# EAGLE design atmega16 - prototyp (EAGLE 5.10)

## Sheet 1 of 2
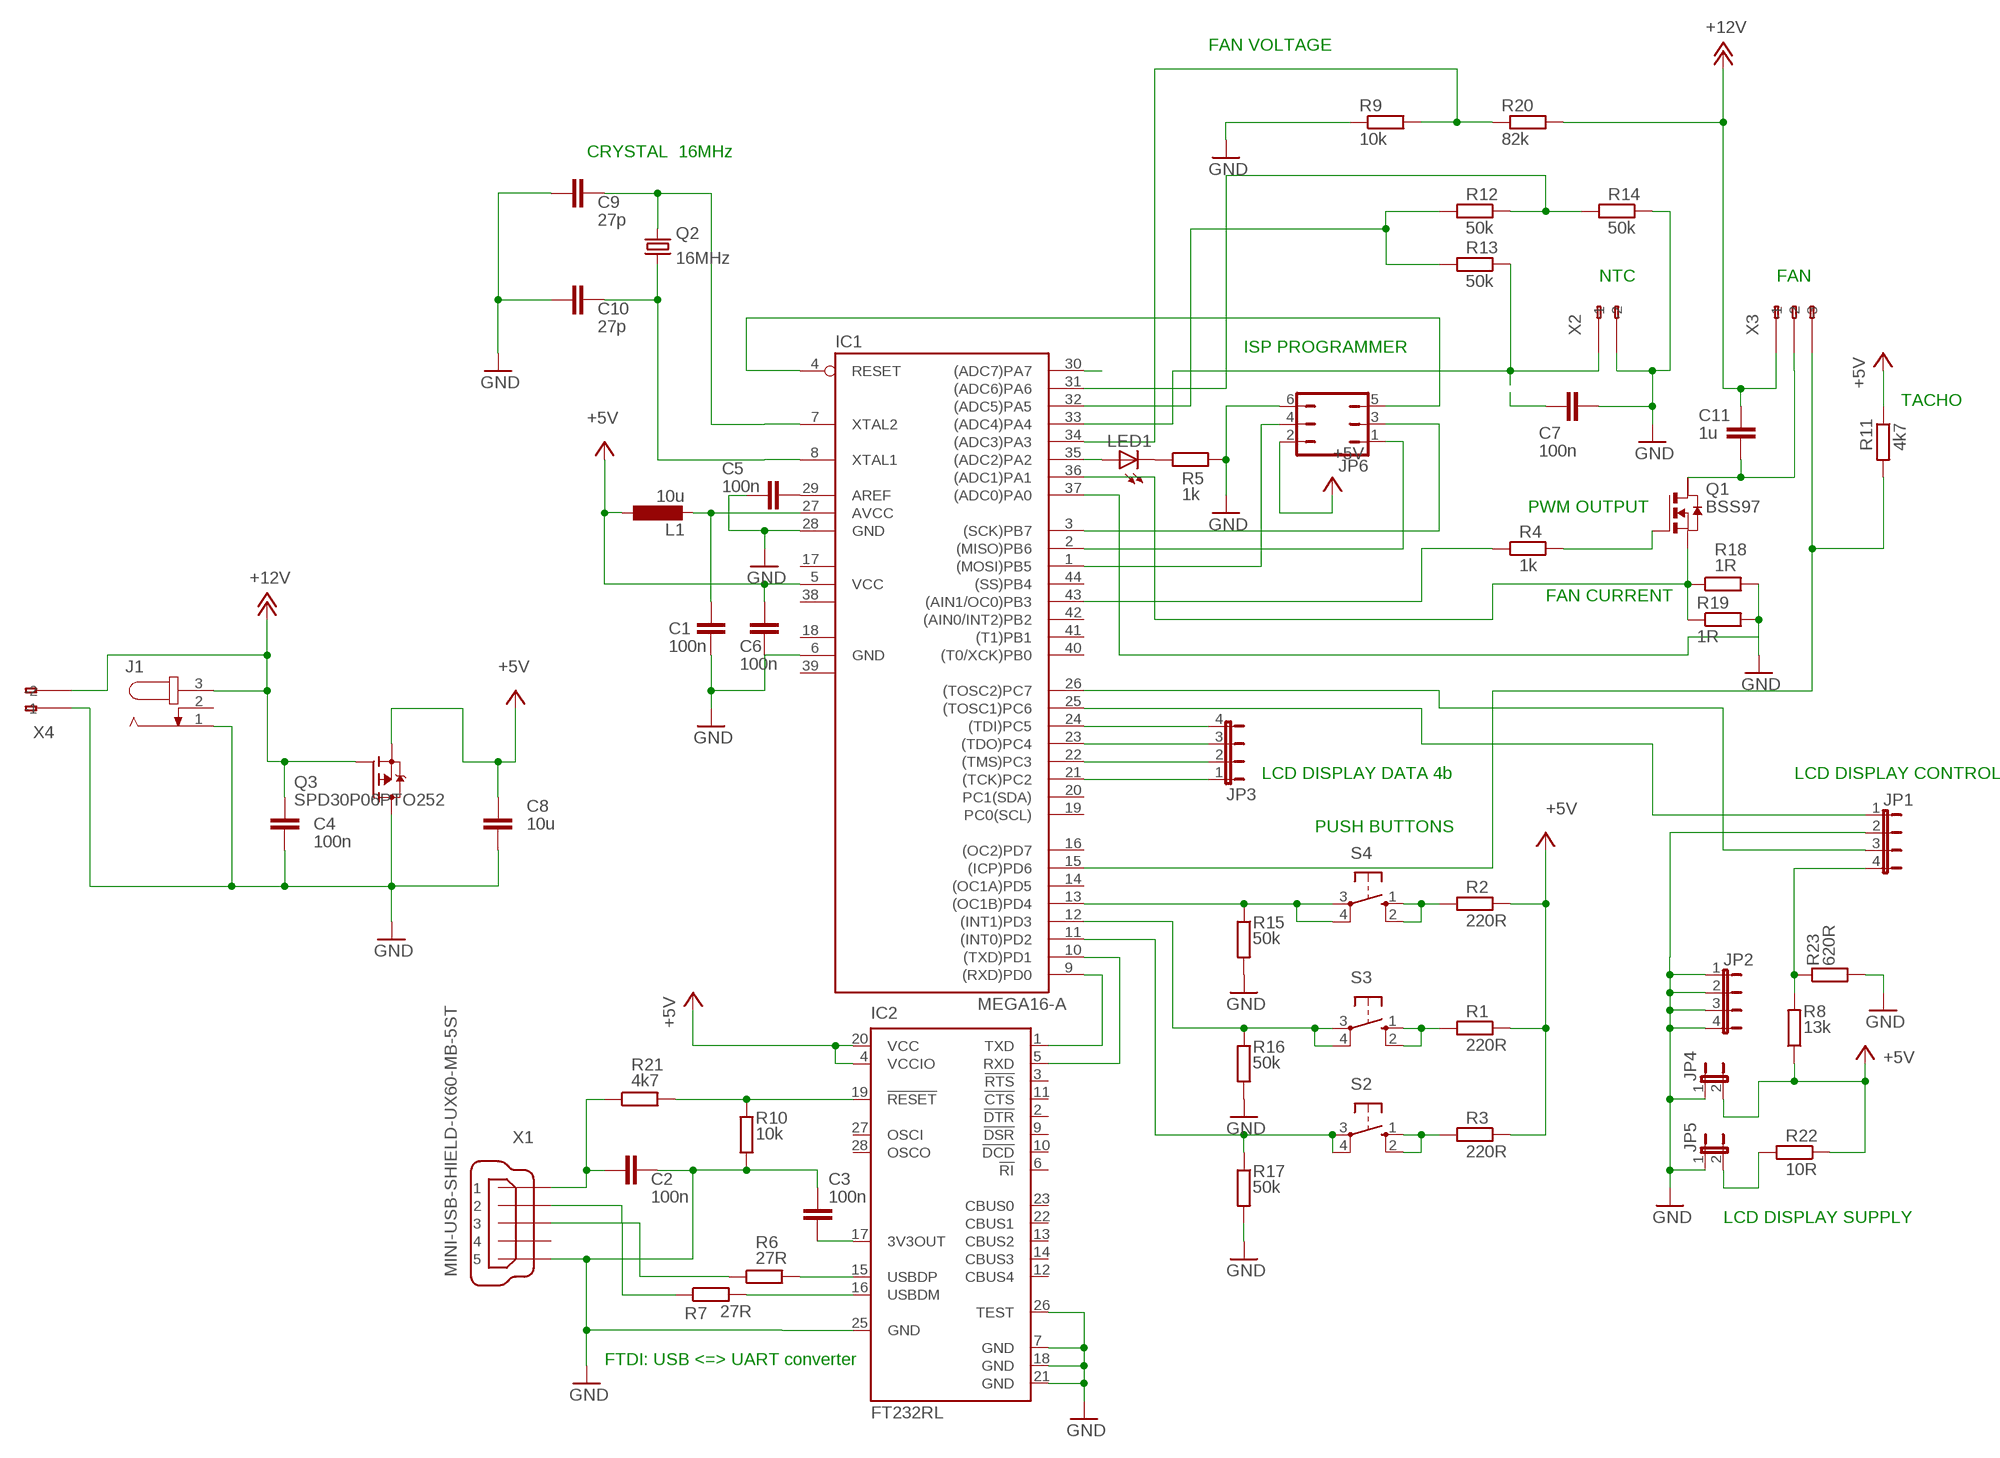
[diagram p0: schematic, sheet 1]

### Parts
C1  100n  C-EUC0805K  [C0805K]
C2  100n  C-EUC0805K  [C0805K]
C3  100n  C-EUC0805K  [C0805K]
C4  100n  C-EUC0805K  [C0805K]
C5  100n  C-EUC0805K  [C0805K]
C6  100n  C-EUC0805K  [C0805K]
C7  100n  C-EUC0805K  [C0805K]
C8  10u  C-EUC0805K  [C0805K]
C9  27p  C-EUC0805K  [C0805K]
C10  27p  C-EUC0805K  [C0805K]
C11  1u  C-EUC0805K  [C0805K]
IC1  MEGA16-A  [TQFP44]
IC2  FT232RL  [SSOP28]
J1  JACK-PLUG0  [SPC4077]
JP1  JP4E  [JP4]
JP2  JP4E  [JP4]
JP3  JP4E  [JP4]
JP4  JP1E  [JP1]
JP5  JP1E  [JP1]
JP6  JP3Q  [JP3Q]
L1  10u  L-EU0204/7  [0204/7]
LED1  LED5MM  [LED5MM]
Q1  BSS97  NMOSSOT223  [SOT223]
Q2  16MHz  CRYSTALHC49S  [HC49/S]
Q3  SPD30P06PTO252  [TO252]
R1  220R  R-EU_R0805  [R0805]
R2  220R  R-EU_R0805  [R0805]
R3  220R  R-EU_R0805  [R0805]
R4  1k  R-EU_R0805  [R0805]
R5  1k  R-EU_R0805  [R0805]
R6  27R  R-EU_R0805  [R0805]
R7  27R  R-EU_R0805  [R0805]
R8  13k  R-EU_R0805  [R0805]
R9  10k  R-EU_R0805  [R0805]
R10  10k  R-EU_R0805  [R0805]
R11  4k7  R-EU_0207/10  [0207/10]
R12  50k  R-EU_R0805  [R0805]
R13  50k  R-EU_R0805  [R0805]
R14  50k  R-EU_R0805  [R0805]
R15  50k  R-EU_R0805  [R0805]
R16  50k  R-EU_R0805  [R0805]
R17  50k  R-EU_R0805  [R0805]
R18  1R  R-EU_R0805  [R0805]
R19  1R  R-EU_R1206  [R1206]
R20  82k  R-EU_R0805  [R0805]
R21  4k7  R-EU_R0805  [R0805]
R22  10R  R-EU_0207/10  [0207/10]
R23  620R  R-EU_R0805  [R0805]
S2  10-XX  [B3F-10XX]
S3  10-XX  [B3F-10XX]
S4  10-XX  [B3F-10XX]
X1  MINI-USB-SHIELD-UX60-MB-5ST  [UX60-MB-5ST]
X2  233-102  [233-102]
X3  233-103  [233-103]
X4  233-102  [233-102]

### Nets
+5V: C6.1 C8.1 IC1.5(VCC) IC2.4(VCCIO) IC2.20(VCC) JP4.2 JP6.2 L1.1 Q3.2(S) R1.1 R2.1 R3.1 R8.1 R11.1 R22.1
+12V: C4.1 C11.1 J1.3 Q3.1(G) R20.2 X3.A1(-1) X4.A2(-2)
BUTTON1: IC1.11((INT0)PD2) R17.1 S2.3(P) S2.4(P1)
BUTTON2: IC1.12((INT1)PD3) R16.1 S3.3(P) S3.4(P1)
BUTTON3: IC1.13((OC1B)PD4) R15.1 S4.3(P) S4.4(P1)
GND: C1.2 C2.2 C3.2 C4.2 C5.2 C6.2 C7.1 C8.2 C9.2 C10.2 IC1.6(GND) IC1.28(GND) IC1.37((ADC0)PA0) IC2.7(GND) IC2.18(GND) IC2.21(GND) IC2.25(GND) IC2.26(TEST) J1.1 JP1.2 JP2.1 JP2.2 JP2.3 JP2.4 JP4.1 JP5.1 JP6.6 Q3.3(D) R5.2 R9.1 R10.2 R14.1 R15.2 R16.2 R17.2 R18.2 R19.2 R23.2 X1.5 X2.A2(-2) X4.A1(-1)
N$1: C5.1 IC1.29(AREF)
N$2: IC1.32((ADC5)PA5) R12.2 R13.2
N$3: C11.2 Q1.4(D) X3.A2(-2)
N$4: Q1.1(G) R4.2
N$5: IC1.43((AIN1/OC0)PB3) R4.1
N$6: IC1.9((RXD)PD0) IC2.1(TXD)
N$7: IC1.2((MISO)PB6) JP6.1
N$8: IC1.3((SCK)PB7) JP6.3
N$9: IC1.4(RESET) JP6.5
N$10: IC1.26((TOSC2)PC7) JP1.3
N$11: IC1.25((TOSC1)PC6) JP1.1
N$12: IC1.24((TDI)PC5) JP3.4
N$13: IC1.30((ADC7)PA7)
N$14: IC1.31((ADC6)PA6) R12.1 R14.2
N$16: IC1.10((TXD)PD1) IC2.5(RXD)
N$17: IC1.15((ICP)PD6) R11.2 X3.A3(-3)
N$18: R2.2 S4.1(S) S4.2(S1)
N$19: R1.2 S3.1(S) S3.2(S1)
N$20: R3.2 S2.1(S) S2.2(S1)
N$21: IC1.23((TDO)PC4) JP3.3
N$22: IC1.22((TMS)PC3) JP3.2
N$23: IC1.1((MOSI)PB5) JP6.4
N$24: IC1.21((TCK)PC2) JP3.1
N$25: JP5.2 R22.2
N$26: C2.1 R21.1 X1.1
N$27: IC2.16(USBDM) R7.2
N$28: IC2.15(USBDP) R6.2
N$29: IC1.36((ADC1)PA1) Q1.3(S) R18.1 R19.1
N$30: IC1.34((ADC3)PA3) R9.2 R20.1
N$31: R7.1 X1.2
N$32: R6.1 X1.3
N$33: C1.1 IC1.27(AVCC) L1.2
N$34: JP1.4 R8.2 R23.1
N$35: IC2.19(!RESET) R10.1 R21.2
N$36: C3.1 IC2.17(3V3OUT)
N$37: C10.1 IC1.8(XTAL1) Q2.1
N$38: C9.1 IC1.7(XTAL2) Q2.2
N$45: LED1.K(C) R5.1
N$46: IC1.35((ADC2)PA2) LED1.A
N$47: C7.2 IC1.33((ADC4)PA4) R13.1 X2.A1(-1)
Unconnected: IC1.14((OC1A)PD5) IC1.16((OC2)PD7) IC1.19(PC0(SCL)) IC1.20(PC1(SDA)) IC1.40((T0/XCK)PB0) IC1.41((T1)PB1) IC1.42((AIN0/INT2)PB2) IC1.44((SS)PB4) IC2.2(!DTR) IC2.3(!RTS) IC2.6(!RI) IC2.9(!DSR) IC2.10(!DCD) IC2.11(!CTS) IC2.12(CBUS4) IC2.13(CBUS2) IC2.14(CBUS3) IC2.22(CBUS1) IC2.23(CBUS0) IC2.27(OSCI) IC2.28(OSCO) J1.2 Q1.2(D2) X1.4 X1.M1(S1) X1.M2(S2) X1.M3(S3) X1.M4(S4) X2.B1(B-1) X2.B2(B-2) X3.B1(B-1) X3.B2(B-2) X3.B3(B-3) X4.B1(B-1) X4.B2(B-2)

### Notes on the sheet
- FAN VOLTAGE
- CRYSTAL  16MHz
- NTC | FAN
- ISP PROGRAMMER
- TACHO
- PWM OUTPUT
- FAN CURRENT
- LCD DISPLAY DATA 4b | LCD DISPLAY CONTROL
- PUSH BUTTONS
- LCD DISPLAY SUPPLY
- FTDI: USB <=> UART converter

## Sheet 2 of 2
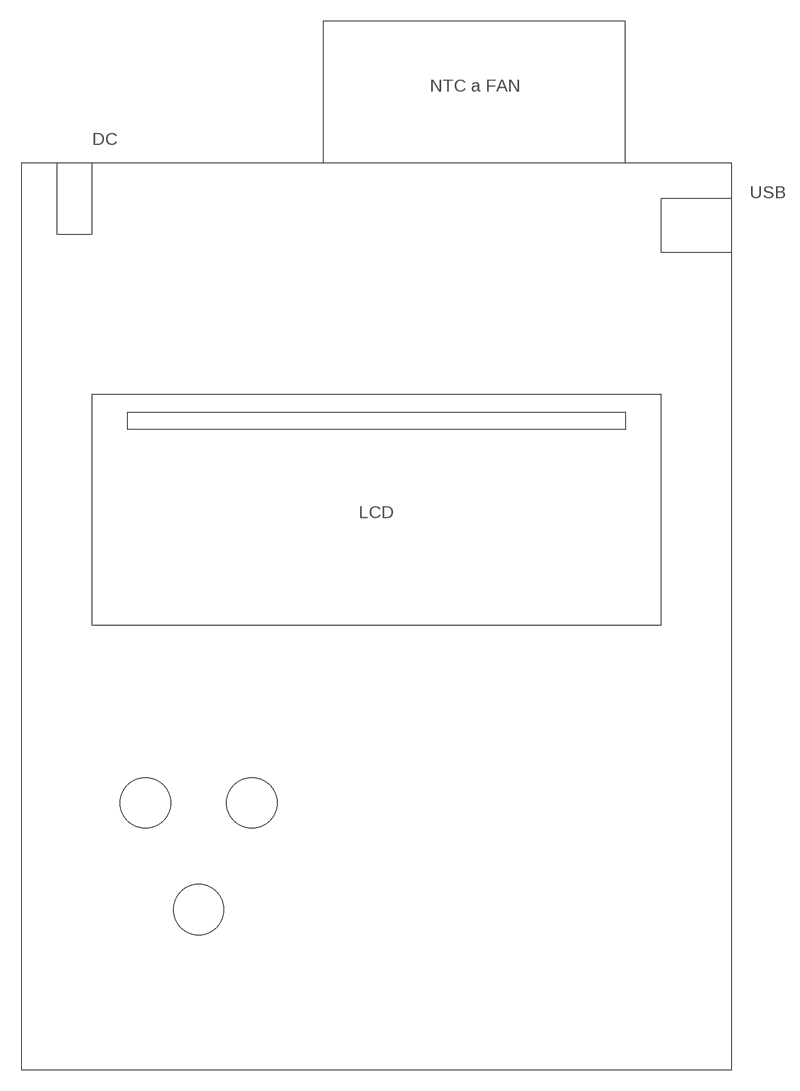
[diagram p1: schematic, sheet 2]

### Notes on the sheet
- NTC a FAN
- DC
- USB
- LCD

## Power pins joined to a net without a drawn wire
GND1: IC1.18(GND1)
GND2: IC1.39(GND2)
VCC1: IC1.17(VCC1)
VCC2: IC1.38(VCC2)

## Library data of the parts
C1-C11 = rcl:C-EU: CAPACITOR, European symbol
IC1 = atmel:MEGA16: MICROCONTROLLER 16 Kbytes FLASH 1 kbytes SRAM 512 bytes EEPROM USART 8-channel 10 bit ADC Source: avr.lbr
IC2 = ftdichip:FT232R: Source: http://www.ftdichip.com/Documents/DataSheets/DS_FT232R_v104.pdf
J1 = con-jack:JACK-PLUG: DC POWER JACK Power Jack, DC, Right Angle, Through Hole, Rated 5A at 16VDC, PC Terminals Distributor: Farnell (www.Farnell.de) Drawing: 84N1161.pdf / 84N1162.pdf Manufacturer: SPC Technology (www.spctechnology.com) Type: SPC4077 / SPC 4078
JP1-JP3 = jumper:JP4E: JUMPER
JP4 JP5 = jumper:JP1E: JUMPER
JP6 = jumper:JP3Q: JUMPER
L1 = rcl:L-EU: INDUCTOR, European symbol
LED1 = led:LED: LED
Q1 = zetex:NMOSSOT223: MOS FET
Q2 = crystal:CRYSTAL: CRYSTAL
Q3 = transistor-fet:SPD30P06P: SIPMOS(R) Power-Transistor P-Channel, Enhancement mode Source: http://www.infineon.com/upload/Document/cmc_upload/documents/012/3615/SPD_U30P06P.pdf
R1-R23 = rcl:R-EU_: RESISTOR, European symbol
S2-S4 = switch-omron:10-XX: OMRON SWITCH
X1 = con-hirose:MINI-USB-SHIELD-: MINI USB Connector Source: http://www.hirose.co.jp/cataloge_hp/e24000019.pdf
X2 X4 = con-wago255:233-102: WAGO
X3 = con-wago255:233-103: WAGO

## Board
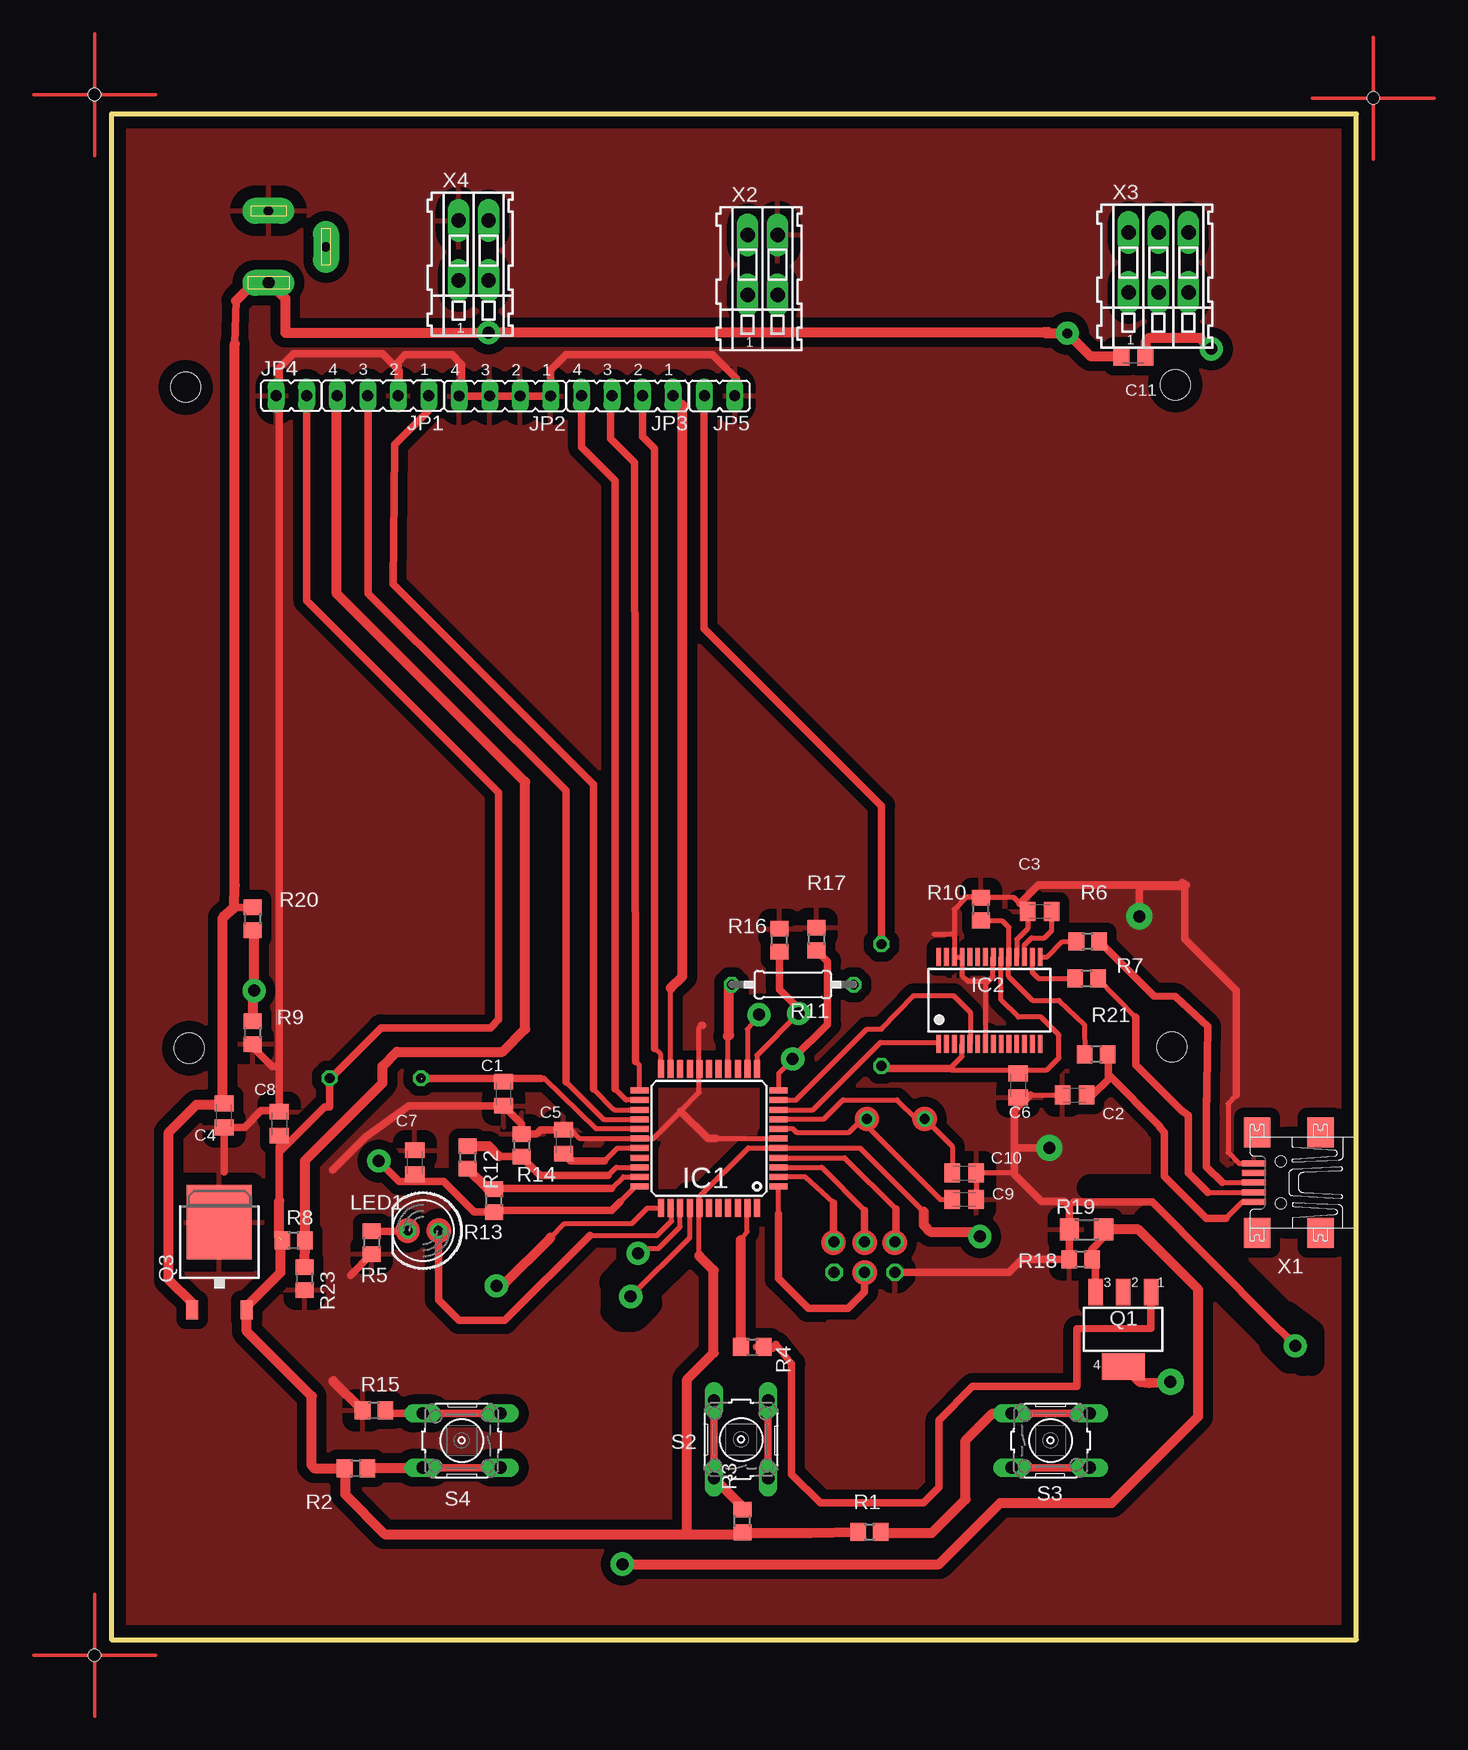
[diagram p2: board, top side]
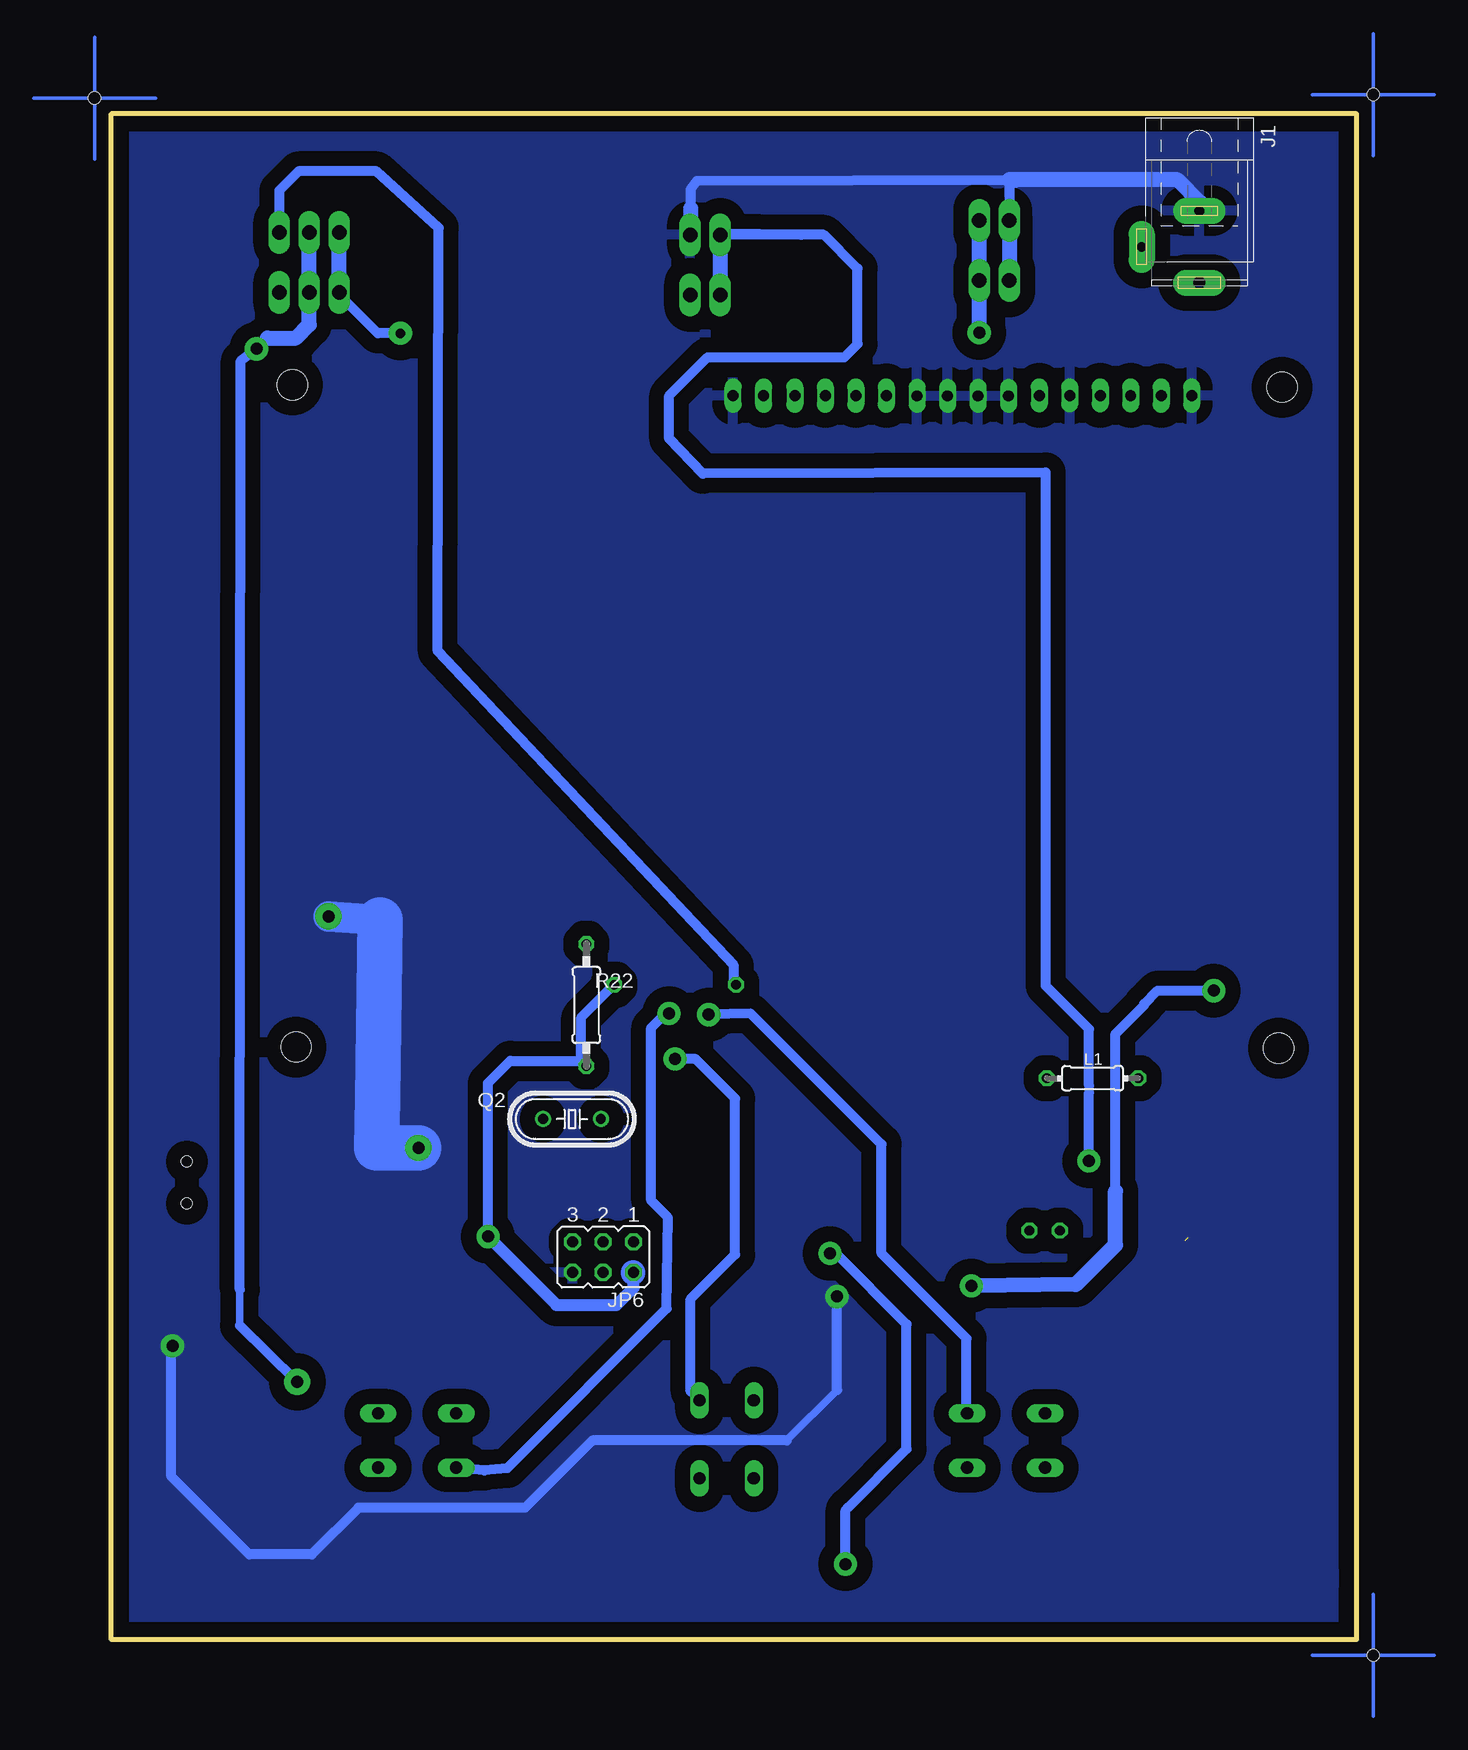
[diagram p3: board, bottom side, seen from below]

Size 103.8 x 127.2 mm. Coordinates in mm from the lower left corner, seen from the top.
Outline: 0,0 103.8,0 103.8,127.2 0,127.2 0,0
Copper layers (1*16): Top 0.035mm / dielectric 1.5mm / Bottom 0.035mm
Design rules "default *": minimum track width 10mil, minimum drill 24mil, track to track 8mil, track to pad 8mil, pad to pad 8mil, via to via 8mil, smd to smd 8mil, copper to edge 40mil, drill to drill 8mil, minimum pad ring 10mil, minimum via ring 8mil, stop-mask expansion 4mil, vias tented up to drill 0mil, thermal gap 40mil
Holes 2.5 mm at 6.5,49.3 6.2,104.4 88.7,104.6 88.4,49.4
tRestrict: 32 lines

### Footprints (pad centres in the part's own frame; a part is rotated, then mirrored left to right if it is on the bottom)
C0805K = smd 1.3 x 1.6: 1 -1,0; 2 1,0
TQFP44 = smd 1.5 x 0.5: 1 -5.8,4; 2 -5.8,3.2; 3 -5.8,2.4; 4 -5.8,1.6; 5 -5.8,0.8; 6 -5.8,0; 7 -5.8,-0.8; 8 -5.8,-1.6; 9 -5.8,-2.4; 10 -5.8,-3.2; 11 -5.8,-4; 23 5.8,-4; 24 5.8,-3.2; 25 5.8,-2.4; 26 5.8,-1.6; 27 5.8,-0.8; 28 5.8,0; 29 5.8,0.8; 30 5.8,1.6; 31 5.8,2.4; 32 5.8,3.2; 33 5.8,4 | smd 0.5 x 1.5: 12 -4,-5.8; 13 -3.2,-5.8; 14 -2.4,-5.8; 15 -1.6,-5.8; 16 -0.8,-5.8; 17 0,-5.8; 18 0.8,-5.8; 19 1.6,-5.8; 20 2.4,-5.8; 21 3.2,-5.8; 22 4,-5.8; 34 4,5.8; 35 3.2,5.8; 36 2.4,5.8; 37 1.6,5.8; 38 0.8,5.8; 39 0,5.8; 40 -0.8,5.8; 41 -1.6,5.8; 42 -2.4,5.8; 43 -3.2,5.8; 44 -4,5.8
SSOP28 = smd 0.4 x 1.5: 1 -4.225,-3.625; 2 -3.575,-3.625; 3 -2.925,-3.625; 4 -2.275,-3.625; 5 -1.625,-3.625; 6 -0.975,-3.625; 7 -0.325,-3.625; 8 0.325,-3.625; 9 0.975,-3.625; 10 1.625,-3.625; 11 2.275,-3.625; 12 2.925,-3.625; 13 3.575,-3.625; 14 4.225,-3.625; 15 4.225,3.625; 16 3.575,3.625; 17 2.925,3.625; 18 2.275,3.625; 19 1.625,3.625; 20 0.975,3.625; 21 0.325,3.625; 22 -0.325,3.625; 23 -0.975,3.625; 24 -1.625,3.625; 25 -2.275,3.625; 26 -2.925,3.625; 27 -3.575,3.625; 28 -4.225,3.625
SPC4077 = drill 0.8 pad 2.184 long: 1 -3,0; 2 0,-4.8 | drill 1 pad 2.184 long: 3 3,0
JP4 = drill 0.914 long: 1 -3.81,0; 2 -1.27,0; 3 1.27,0; 4 3.81,0
JP1 = drill 0.914 long: 1 0,-1.27; 2 0,1.27
JP3Q = drill 0.914 octagon: 1 -2.54,-1.27; 2 -2.54,1.27; 3 0,-1.27; 4 0,1.27; 5 2.54,-1.27; 6 2.54,1.27
0204/7 = drill 0.813 octagon: 1 -3.81,0; 2 3.81,0
LED5MM = drill 0.813 octagon: A -1.27,0; K 1.27,0
SOT223 = smd 1.219 x 2.235: 1 -2.311,-3.099; 2 0,-3.099; 3 2.311,-3.099 | smd 3.6 x 2.2: 4 0,3.099
HC49/S = drill 0.813 round: 1 -2.413,0; 2 2.413,0
TO252 = smd 1 x 1.6: 1 -2.28,-4.8; 2 2.28,-4.8 | smd 5.4 x 6.2: 3 0,2.5
R0805 = smd 1.3 x 1.5: 1 -0.95,0; 2 0.95,0
0207/10 = drill 0.813 octagon: 1 -5.08,0; 2 5.08,0
R1206 = smd 1.6 x 1.803: 1 -1.422,0; 2 1.422,0
B3F-10XX = drill 1.016 long: 1 -3.251,2.261; 2 3.251,2.261; 3 -3.251,-2.261; 4 3.251,-2.261
SESAZOVACI = hole 1.016: 0,0
UX60-MB-5ST = smd 2 x 0.5: 1 2.25,1.6; 2 2.25,0.8; 3 2.25,0; 4 2.25,-0.8; 5 2.25,-1.6 | smd 2.2 x 2.5: M1 -3.3,-4.2; M2 -3.3,4.2; M3 2,4.2; M4 2,-4.2 | hole 0.9: 0,-1.75; 0,1.75
233-102 = drill 1.2 long: A1 -1.25,2.5; A2 1.25,2.5; B1 -1.25,-2.5; B2 1.25,-2.5
233-103 = drill 1.2 long: A1 -2.5,2.5; A2 0,2.5; A3 2.5,2.5; B1 -2.5,-2.5; B2 0,-2.5; B3 2.5,-2.5

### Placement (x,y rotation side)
C1  32.7,45.5 270 top
C2  80.3,45.4 180 top
C3  77.4,60.7 180 top
C4  9.4,43.7 270 top
C5  37.7,41.5 90 top
C6  75.6,46.2 270 top
C7  25.3,39.8 270 top
C8  14,43 90 top
C9  71.1,36.7 0 top
C10  71.1,38.9 0 top
C11  85.2,107 0 top
IC1  49.82,41.78 180 top
IC2  73.2,53.3 0 top
J1  13.1,116.1 270 bottom
JP1  22.64,103.72 180 top
JP2  32.82,103.68 180 top
JP3  43,103.7 180 top
JP4  15,103.7 270 top
JP5  50.7,103.7 90 top
JP6  62.8,31.9 180 bottom
L1  22,46.8 180 bottom
LED1  26,34.1 180 top
Q1  84.36,25.87 180 top
Q2  65.4,43.4 0 bottom
Q3  9,32.3 0 top
R1  63.2,9 0 top
R2  20.4,14.3 0 top
R3  52.6,9.9 90 top
R4  53.44,24.39 0 top
R5  21.7,33.1 270 top
R6  81.4,58.2 180 top
R7  81.3,55.1 180 top
R8  15.2,33.3 0 top
R9  11.8,50.6 90 top
R10  72.5,60.9 90 top
R11  56.8,54.6 180 top
R12  29.7,40.2 270 top
R13  31.9,36.6 90 top
R14  34.2,41.2 270 top
R15  21.9,19.1 180 top
R16  55.7,58.3 90 top
R17  58.8,58.4 90 top
R18  80.8,31.7 180 top
R19  81.3,34.2 180 top
R20  11.8,60.1 90 top
R21  82.1,48.8 180 top
R22  64.2,52.9 90 bottom
R23  16.1,30.1 270 top
S2  52.5,16.7 90 top
S3  78.3,16.6 0 top
S4  29.2,16.6 180 top
U$1  [SESAZOVACI]  -1.4,128.8 0 top
U$2  [SESAZOVACI]  105.2,128.5 0 top
U$3  [SESAZOVACI]  -1.4,-1.3 0 top
X1  97.5,38.1 180 top
X2  54.3,114.6 0 top
X3  87.3,114.8 0 top
X4  30.2,115.8 0 top

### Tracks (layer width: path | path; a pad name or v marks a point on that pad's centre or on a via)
+5V  (via drill 1 pad 1.93)  (1 unrouted)
  Top 0.406: IC2.4 70.92,48.62 69.9,47.6 70,47.5 75.6,47.5 78,47.5 79,48.5 79,50.4 77.5,51.9 75.6,51.9 74.17,53.33 IC2.20 | 49,36 49.07,35.67 | 49,36 49,36.9 53.1,41 55.7,41 55.68,40.98 | 55.68,40.98 IC1.5 | 55.68,40.98 62.42,40.98 67.7,35.7 | 49,32 49,36
  Top 0.61: 75.6,47.5 C6.1 | 14,36.6 14,40.6 | 14,40.6 14,41.1 14.1,41.2 14.1,41.9 C8.1 | 14,40.6 17.79,44.39 18.19,44.39 L1.1 18.29,46.8 22.49,51 31.6,51 32.3,51.7 32.3,70.6 16.3,86.6 16.3,103.67 JP4.2 | 16.7,14.5 16.9,14.3 | R2.1 19.5,14.25 | 69.9,47.6 64.42,47.6 R22.1
  Top 0.813: 67.7,35.7 67.7,34.6 68.3,34 72,34 v72.4,33.6 | 16.9,14.3 R2.1 | 19.5,14.25 19.5,12.1 22.8,8.8 47.8,8.8 | R1.1 58.3,8.9 52.65,8.9 R3.1 52.45,8.8 47.8,8.8 | 49,32 50.2,30.8 50.2,23.9 48,21.7 48,9 47.8,8.8 | 14,33.55 14,36.6 | 16.7,14.5 16.7,20.3 11.3,25.7 11.3,27.48 Q3.2 11.28,27.78 14.1,30.6 14.1,33.15 R8.1
  Bottom 0.813: v72.4,33.6 72.4,46.4 70.55,48.25 64.63,48.25 | 64.63,48.25 R22.1 | 64.63,48.25 64.63,51.85 R11.1
  Bottom 1.016: JP6.2 60.26,29.34 61.7,27.9 66.7,27.9 v72.4,33.6
+12V  (via drill 0.8 pad 1.93, 1 pad 1.93)
  Top 0.61: 10.25,61.05 R20.2 | 9.3,44.6 C4.1 | 10.3,108 10.4,111.6 | 12,113.2 J1.3 | 15.6,109 14.5,109 14.5,108.95 | v31.45,108.95 31.45,109
  Top 0.813: 10.3,108 10.3,62.9 10.25,61.05 9.3,60.2 9.3,44.6 7.1,44.6 4.8,42.3 4.8,30 6.72,28.08 Q3.1 | 10.4,111.6 12,113.2 | 14.5,109 14.5,111.8 J1.3 | 31.45,109 77.8,109 | 77.8,109 78.1,109 | 14.5,108.95 v31.45,108.95 | 77.8,109 77.9,108.9 v79.7,108.9 81.6,107 C11.1
  Bottom 0.813: 84.8,112.4 84.8,112.1 81.6,108.9 v79.7,108.9
  Bottom 1.27: v31.45,108.95 X4.A2 | 84.8,112.4 X3.A1
BUTTON1  (via drill 1 pad 1.93)
  Top 0.406: IC1.11 55.62,47.22 v56.8,48.4
  Top 0.61: S2.3 S2.4 | v56.8,48.4 59.7,51.3 59.7,56.55 R17.1
  Bottom 0.406: S2.4 55.5,20.69
  Bottom 0.813: v56.8,48.4 55.1,48.4 51.8,45.1 51.8,32.1 55.5,28.4 55.5,20.69
BUTTON2  (via drill 1 pad 1.93)
  Top 0.406: IC1.12 53.82,48.72 v57.3,52.2
  Top 0.61: S3.3 S3.4 | v57.3,52.2 57.3,52.6 55.7,54.2 R16.1
  Bottom 0.813: v57.3,52.2 57.6,52.2 58.8,51 58.8,36.6 57.4,35.2 57.5,27.6 70.8,14.3 72.71,14.1 S3.3
BUTTON3  (via drill 1 pad 1.93)
  Top 0.406: IC1.13 53.02,50.88 v54,52.1 | R15.1 22.85,18.86
  Top 0.61: S4.3 S4.4 22.85,18.86
  Bottom 0.406: S4.3 32.5,18.91
  Bottom 0.813: v54,52.1 50.5,52.2 39.6,41.3 39.6,32.2 32.5,25.1 32.5,18.91
GND  (via drill 1 pad 1.93, 1 pad 2.18)
  Top 0.406: 75.9,45.4 76,45.4 76.6,45.4 C2.2 | 72.9,49.65 IC2.7 72.88,54.68 73.1,54.9 | IC2.18 75.47,58.38 76.4,59.3 C3.2 75.75,61.35 75.25,61.85 R10.2 72.45,61.9 71.3,61.9 70.27,60.88 70.27,59 | 73.1,54.9 71.4,54.9 70.92,55.38 IC2.25 IC2.26 70.27,59 | 73.1,54.9 73.5,55.3 73.5,56.9 IC2.21 | 68.6,58.8 70.08,58.8 70.27,59 | 50.42,41.78 IC1.6 | 75.3,38.8 75.2,38.9 C10.2 C9.2 | IC1.37 48.22,33.52 v43.3,28.6 | 80.26,36.5 79.88,36.12 | X1.5 94,39.7 93.1,40.6 93.1,44.7 93.8,45.4 | 49.2,51.2 49,51 49,45.6 47.45,44.05 45.18,41.78 IC1.28 44,41.8 39,41.8 38.1,42.7
  Top 0.61: 89.5,62.8 89.5,58.4 93.8,54.1 93.8,45.4 | 89.6,62.9 77.3,62.9 75.75,61.35 | 89.5,62.8 89.6,62.9 | 75.3,41 75.3,38.8 77.55,36.55 79.45,36.55 79.88,36.12 R19.2 79.85,34.17 R18.2 75.9,31.7 74.83,30.63 JP6.6 | 75.3,41 75.3,44.1 76.6,45.4 | 89.6,62.9 89.3,63.1 | C6.2 75.8,45.2 76,45.4 | 18.44,39.14 21.2,41.9 24.8,44.5 C1.2 34.2,43 R14.1 35.45,42.15 35.8,42.5 C5.2 37.9,42.5 38.1,42.7 | 13.7,103.67 JP4.1 14,103.43 | 9.4,39 C4.2 11.1,42.7 12.5,44.1 13.9,44.1 C8.2 14,47.8 | 14,47.8 14,103.43 | 14,103.43 14,106 15.2,107.2 22.6,107.2 24,105.8 24,103.81 JP1.2 23.91,106.51 24.5,107.1 28.4,107.1 29.2,106.3 29.2,103.4 29.3,103.3 29.3,103.39 JP2.4 JP2.3 JP2.2 JP2.1 36.63,105.83 37.9,107.1 50.1,107.1 52.1,105.1 52.1,103.83 JP5.1 | 89.5,62.8 85.7,62.8 v85.7,60.3 | 96.65,26.55 86.8,36.5 80.26,36.5 | 96.65,26.55 96.9,26.3 | R9.1 11.8,49.4 13.4,47.8 14,47.8 | 75.3,41 v78.2,41 | 49.2,51.2 49.3,51.2 | 50.42,41.78 49.72,41.78 47.45,44.05 | v98.7,24.5 98.1,25.1 96.65,26.55 | R5.2 19.93,30.38
  Top 0.813: R15.2 18.5,21.55
  Bottom 0.61: 47.5,16.6 43.3,20.8
  Bottom 0.813: 43.3,20.8 v43.3,28.6 | 47.5,16.6 63.7,16.6 69.3,11 83.2,11 87.1,7.1 92.3,7.1 98.8,13.6 98.8,23.9 v98.7,24.5 | X4.A1 28.95,121.65 55,121.59 55.5,120.89 55.5,119.3 | 55.5,117 55.5,117.05 X2.A2
  Bottom 1.27: 55.5,119.3 55.5,117 | 13,119.1 13,119.8 14.9,121.7 28.4,121.7 | 28.4,121.7 29,121.7 | 28.95,121.65 28.45,121.65 28.4,121.7
  Bottom 2.54: 81.4,60 v85.7,60.3
  Bottom 3.81: v78.2,41 81.7,41 81.6,45.1 81.4,60
  pour Top: 59.8,26.5 64.2,26.5 64.2,12.8 59.8,12.8
  pour Top: 76.1,9.1 80.1,9.1 80.1,5.5 76.1,5.5
  pour Top: 21.8,125.8 36.6,125.8 36.5,121.5 21.7,121.5
  pour Top: 44,125.7 67.1,125.8 67.2,121.1 44.1,121
  pour Top: 62.8,121.8 80.6,121.7 80.6,111 62.8,111.1
  pour Top: 80.9,124.4 93.4,124.4 93.4,120.3 80.9,120.3
  pour Top (isolate 0.813): -0.8,129 106.6,129 106.6,-1.6 -0.8,-1.6
  pour Top: 52.1,95 85.3,95 85.8,85.1 52.2,85.1
  pour Bottom (isolate 1.27): -3.6,128.3 106.2,128.3 106.2,-2.8 -3.6,-2.8
  pour Bottom: 1.7,10.4 14.9,10.3 14.8,4.3 1.6,4.4
N$1
  Top 0.406: IC1.29 42.18,40.98 41.1,39.9
  Top 0.61: 41.1,39.9 38.3,39.9 C5.1
N$2
  Top 0.406: IC1.32 42.68,38.58 41.7,37.6
  Top 0.61: 41.7,37.6 31.95,37.6 R13.2
  Top 0.813: 31.95,37.6 31.35,37.6 R12.2
N$3  (via drill 1 pad 1.93, 1 pad 2.18)
  Top 0.813: v88.3,21.5 86.5,21.4 85.7,21.5 84.4,22.73 Q1.4 | C11.2 86.2,108.2 86.5,108.5 90.8,108.5 v91.7,107.6
  Bottom 0.61: 93.1,26.2 93.1,29.2
  Bottom 0.813: v88.3,21.5 93.1,26.2 | 93.1,29.2 93,106.6 v91.7,107.6 90.8,108.5
  Bottom 1.27: 90.8,108.5 88.4,108.5 87.3,109.6 X3.A2
N$4
  Top 0.61: Q1.1 86.67,25.97 80.5,25.9 80.5,21.1 71.8,21.1 69,18.3 69,12.7 67.7,11.4 59.1,11.4 56.7,13.8 56.7,23 55.4,24.6 55.1,24.3 R4.2 53.8,24.4
N$5
  Top 0.406: 52.49,33.31 53,34 53,35.96 IC1.43
  Top 0.813: R4.1 52.49,33.31
N$6
  Top 0.406: IC1.9 58.48,44.18 64.1,49.8 68.85,49.8 IC2.1
N$7
  Top 0.406: IC1.2 57.82,38.58 60.2,36.4
  Top 0.61: 60.2,36.4 60.2,33.23 JP6.1
N$8
  Top 0.406: IC1.3 59.22,39.38 62.8,35.8
  Top 0.61: 62.8,35.8 JP6.3
N$9
  Top 0.406: IC1.4 61.12,40.18 65.4,35.9
  Top 0.61: 65.4,35.9 65.4,33.33 JP6.5
N$10
  Top 0.406: IC1.26 41.02,43.38 37.9,46.5
  Top 0.61: 37.9,46.5 37.9,70.8 21.4,87.2 21.4,103.69 JP1.3
N$11
  Top 0.406: IC1.25 41.92,44.18 40.2,45.9
  Top 0.61: 40.2,45.9 40.2,71.3 23.5,88 23.6,99.17 23.6,99.6 26.4,102.4 26.4,103.67 JP1.1
N$12
  Top 0.406: IC1.24 42.92,44.98 42,45.9
  Top 0.61: 42,45.9 42,96.6 39.2,99.4 JP3.4
N$14
  Top 0.406: IC1.31 42.08,39.38 41.4,38.7
  Top 0.61: 32.3,40.3 34.15,40.3 R14.2 35.75,38.7 41.4,38.7
  Top 0.813: R12.1 31.45,41.15 32.3,40.3
N$15
  pour Top (hatched): 20.1,24.9 44.8,25 44.8,20.8 20.9,20.9
N$16
  Top 0.406: IC1.10 57.08,44.98 63,50.9 64.2,50.9 66.9,53.7 70.2,53.7 71.6,52.3 71.6,49.7 IC2.5
N$17
  Top 0.406: 51.4,50.3 51.4,47.6 IC1.15
  Top 0.813: 51.4,50.3 51.5,50.4 51.5,54.38 R11.2
  Bottom 0.813: X3.A3 89.8,120.8 88.2,122.4 81.7,122.4 76.5,117.7 76.6,82.4 51.9,56.2 51.9,54.78 R11.2
N$18
  Top 0.61: R2.2 21.39,14.34 | S4.2 S4.1
  Top 0.813: 21.39,14.34 S4.2
N$19
  Top 0.61: S3.1 S3.2
  Top 0.813: S3.1 73.46,18.86 71.2,16.6 71.2,11.7 68.4,8.9 64.25,8.9 R1.2
N$20
  Top 0.61: S2.1 S2.2
  Top 0.813: R3.2 52.6,11.09 S2.1
N$21
  Top 0.406: IC1.23 44.02,47.88 43.7,48.2
  Top 0.61: 43.7,48.2 43.6,98.1 41.6,100.1 41.6,103.57 JP3.3
N$22
  Top 0.406: IC1.22 45.82,48.78 45.3,49.3
  Top 0.61: 45.3,49.3 45.3,99.3 44.3,100.3 44.3,103.67 JP3.2
N$23
  Top 0.406: IC1.1 55.62,35.52 55.6,35.5
  Top 0.61: 55.6,35.5 55.6,30.1 58.1,27.6 61.4,27.6 62.8,29 JP6.4
N$24
  Top 0.406: IC1.21 46.62,54.32
  Top 0.61: 47.6,102.91 JP3.1
  Top 0.813: 46.62,54.32 47.6,55.3 47.6,102.91
N$25
  Top 0.61: 64.2,69.5 64,69.7 | 64,69.7 49.4,84.3 49.4,103.67 JP5.2 | R22.2 64.2,69.5 | 64.2,69.5 64,69.7
N$26
  Top 0.406: 92.9,35.1 94.3,36.5 X1.1
  Top 0.61: C2.1 81.8,45.4 83.1,46.7 83.1,47.1 | 83.1,47.1 83.1,48.75 R21.1 | 83.1,47.1 87.4,42.8 87.4,42.7 87.8,42.3 87.8,38.6 89.9,36.5 91.3,35.1 92.9,35.1
N$27
  Top 0.406: R7.2 77.3,55.1 76.8,55.6 76.8,56.9 IC2.16
N$28
  Top 0.406: IC2.15 78.02,56.93 79.3,58.2 R6.2
N$29  (via drill 1 pad 1.93)
  Top 0.406: IC1.36 47.42,34.42 45.6,32.6 44.3,32.6 v43.9,32.2
  Top 0.61: R19.1 82.8,34.12 82.8,33.6 81.75,32.55 R18.1 82.05,31.4 Q1.3
  Top 0.813: R19.1 85.6,34.2 90.6,29.2 90.6,18.6 83.4,11.4 74.1,11.4 69,6.3 v42.6,6.3
  Bottom 0.61: 42.6,10.8 42.4,11
  Bottom 0.813: v43.9,32.2 43.4,32.2 37.5,26.3 37.5,15.9 42.4,11 | v42.6,6.3 42.6,10.8
N$30  (via drill 1 pad 1.93)
  Top 0.406: IC1.34 44.68,35.98 43.4,34.7 37.8,34.7 36.6,33.5 | 11.9,59.05 R20.1
  Top 0.61: v11.9,54.1 11.8,54
  Top 0.813: 11.8,54 R9.2 | v11.9,54.1 11.9,59.05 | v32.1,29.5 32.7,29.5 32.7,29.6 36.6,33.5
  Bottom 0.61: 17.7,52.9 17.7,53
  Bottom 0.813: v11.9,54.1 16.6,54.1 17.7,53 | 17.7,52.9 20.1,50.5 20.1,37.4
  Bottom 1.27: v32.1,29.5 23.4,29.6 20.1,32.9 20.1,37.4
N$31
  Top 0.406: 85.35,51.9 R7.1 | 91.4,37.3 X1.2
  Top 0.61: 85.35,51.9 85.4,51.85 85.4,47.9 89.15,44.15 89.8,43.7 89.8,38.9 91.4,37.3
N$32
  Top 0.406: 92.6,38.1 X1.3
  Top 0.61: 91.3,43.5 91.3,45.1 | 91.3,43.5 91.4,51.1 88.7,53.6 86.9,53.65 R6.1 | 92.6,38.1 91.3,39.4 91.3,43.5
N$33  (1 unrouted)
  Top 0.406: IC1.27 43.84,42.6 40.6,42.6 40.4,42.6 36.1,46.8 35.9,46.7 35.8,46.8
  Top 0.61: 35.8,46.8 33.3,46.8 32.8,46.8 C1.1 32.4,46.8 25.9,46.8
N$34
  Top 0.813: R23.1 R8.2 16.15,39.95 22.6,46.4 22.6,47.8 23.8,49 32.6,49 34.5,50.9 34.5,71.5 18.8,87.2 18.8,103.69 JP1.4
N$35
  Top 0.406: R10.1 72.55,59.9 74.3,59.9 74.83,59.38 IC2.19 74.8,56.9 74.8,55.3 76.8,53.3 79,53.3 81.1,51.3 R21.2
N$36
  Top 0.406: IC2.17 76.12,57.93 76.7,58.5 77.8,58.5 78.4,59.1 C3.1
N$37
  Top 0.406: IC1.8 55.64,43.4 59.4,43.4 61,45 65.5,45 67.1,43.4 Q2.1 70.1,41.11 C10.1
N$38
  Top 0.406: 55.64,42.6 IC1.7 55.64,42.6 | 55.64,42.6 56.8,42.6 57.1,42.3 61.5,42.3 62.6,43.4 Q2.2 63.1,43.29 63.1,42.7 69.1,36.7 C9.1
N$43
  Bottom 1.27: 28.9,113.3 28.9,118.4
N$45
  Top 0.61: R5.1 23.18,34.05 LED1.K
N$46
  Top 0.406: 39.9,33.7 45.5,33.7 46.7,34.9 46.7,35.9 IC1.35
  Top 0.61: LED1.A 27.27,28.33 29,26.6 32.8,26.6 39.9,33.7
N$47  (via drill 1 pad 1.93)
  Top 0.406: IC1.33 43.68,37.78 42.4,36.5 | C7.2 25.2,38.8 25.2,38.2
  Top 0.61: v22.3,39.9 24,38.2 25.2,38.2 27.7,38.2 30.25,35.65 R13.1 32.05,35.8 41.7,35.8 42.4,36.5
  Bottom 0.61: 22.3,46.1 22.3,45.6 22.3,46.2
  Bottom 0.813: v22.3,39.9 22.3,45.6 | 22.3,46.2 22.3,50.9 25.9,54.5 25.9,97.3 54.5,97.2 57.3,100.1 57.3,103.7 54.1,106.9 42.7,106.9 41.6,108 41.6,114.3 44.4,117.1 46.3,117.1 | 46.3,117.1 53,117.2 | 46.3,117.1 X2.A1
  Bottom 1.27: 53,117.2 53.1,111.7
(copper drawn outside any net)
  shapes: Bottom circle x1, Top circle x8

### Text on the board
bStop: -
tRestrict: GND +V | Thermistor | 1 2 3 | 1 FAN + | 2 FAN - | 3 TACHO | MMIA | Cooling System | -/Next Scr | OK/Set | +
bRestrict: Bottom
